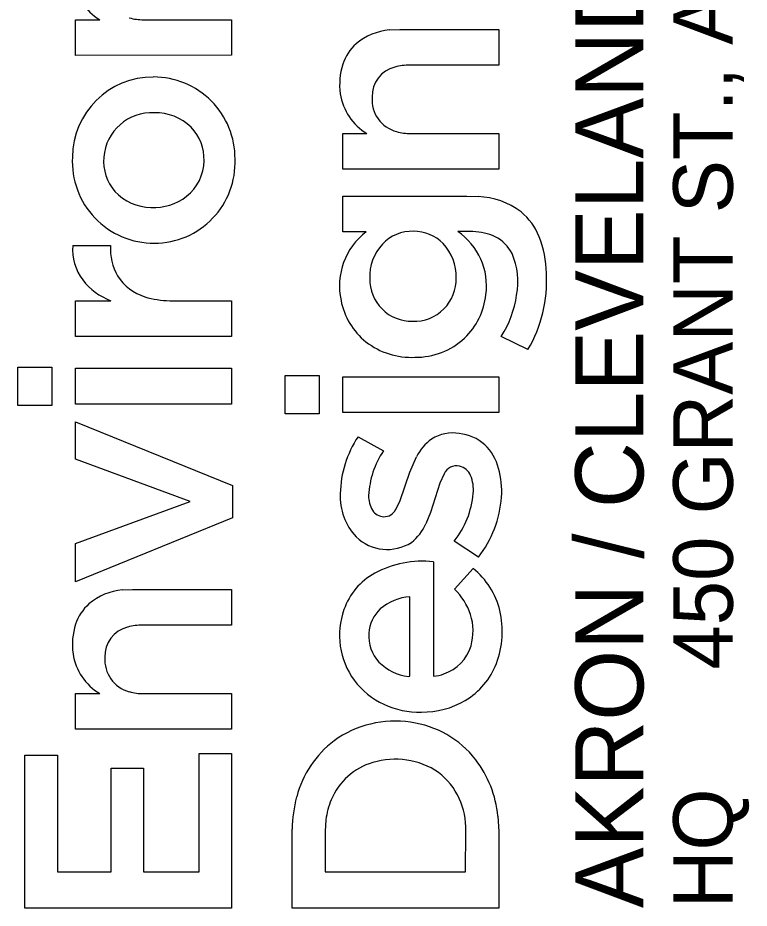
# Model space of a CAD drawing. Extents: x 0 to 34, y 0 to 22.
# Drawn here: x 32.377 to 32.989, y 2.638 to 3.382 of the extents above; entities that cross this region are included whole.
import ezdxf

# ---------------------------------------------------------------- set-up
doc = ezdxf.new("R2010")
doc.units = 0
doc.layers.add('SH_Data', color=7, linetype='Continuous')

msp = doc.modelspace()

# ---------------------------------------------------------------- linework, layer by layer
at = {"layer": 'SH_Data'}
for p, q in [((32.42542, 3.38066), (32.44552, 3.38071)), ((32.42542, 3.35086), (32.42542, 3.38066)), ((32.48222, 3.38071), (32.55569, 3.38071)), ((32.55569, 3.38071), (32.55571, 3.35096)), ((32.68784, 3.3722), (32.69634, 3.37266)), ((32.69634, 3.37266), (32.77916, 3.37266)), ((32.77916, 3.37266), (32.77917, 3.34287)), ((32.55571, 3.35096), (32.42542, 3.35086)), ((32.77917, 3.34287), (32.70485, 3.3428)), ((32.64888, 3.2855), (32.66897, 3.28555)), ((32.64888, 3.25569), (32.64888, 3.2855)), ((32.70568, 3.28555), (32.77915, 3.28555)), ((32.77915, 3.28555), (32.77917, 3.25579)), ((32.77917, 3.25579), (32.64888, 3.25569)), ((32.6489, 3.20336), (32.64889, 3.23322)), ((32.64889, 3.23322), (32.75236, 3.23322)), ((32.75236, 3.23322), (32.76191, 3.23285)), ((32.66836, 3.20336), (32.6489, 3.20336)), ((32.75763, 3.20356), (32.74487, 3.20361)), ((32.42299, 3.19193), (32.45454, 3.19193)), ((32.42542, 3.14577), (32.45473, 3.14579)), ((32.42542, 3.11593), (32.42542, 3.14577)), ((32.50413, 3.14581), (32.55571, 3.14573)), ((32.55571, 3.14573), (32.55565, 3.11593)), ((32.55565, 3.11593), (32.42542, 3.11593)), ((32.8036, 3.10491), (32.7812, 3.11598)), ((32.37705, 3.05818), (32.37705, 3.09026)), ((32.37705, 3.09026), (32.40543, 3.09026)), ((32.40543, 3.09026), (32.40543, 3.05818)), ((32.42542, 3.05942), (32.42542, 3.08928)), ((32.42542, 3.08928), (32.55571, 3.08928)), ((32.55571, 3.08928), (32.55571, 3.05942)), ((32.60051, 3.05111), (32.60051, 3.08319)), ((32.60051, 3.08319), (32.62889, 3.08319)), ((32.62889, 3.08319), (32.62889, 3.05111)), ((32.64888, 3.05234), (32.64888, 3.0822)), ((32.64888, 3.0822), (32.77917, 3.0822)), ((32.77917, 3.0822), (32.77917, 3.05234)), ((32.40543, 3.05818), (32.37705, 3.05818)), ((32.55571, 3.05942), (32.42542, 3.05942)), ((32.77917, 3.05234), (32.64888, 3.05234)), ((32.62889, 3.05111), (32.60051, 3.05111)), ((32.42542, 3.01327), (32.42542, 3.0446)), ((32.42542, 3.0446), (32.5567, 2.9913)), ((32.66151, 3.03207), (32.68268, 3.02025)), ((32.70483, 3.00258), (32.71036, 3.01526)), ((32.52117, 2.97798), (32.42542, 3.01327)), ((32.69675, 2.97868), (32.70483, 3.00258)), ((32.73342, 3.00101), (32.72985, 2.9933)), ((32.72985, 2.9933), (32.72213, 2.96882)), ((32.5567, 2.9913), (32.5567, 2.96441)), ((32.42542, 2.94294), (32.52117, 2.97798)), ((32.69299, 2.97117), (32.69675, 2.97868)), ((32.5567, 2.96441), (32.42542, 2.91086)), ((32.72213, 2.96882), (32.71822, 2.95921)), ((32.42542, 2.91086), (32.42542, 2.94294)), ((32.76214, 2.93141), (32.74198, 2.94469)), ((32.72453, 2.92747), (32.72463, 2.83195)), ((32.74228, 2.90465), (32.75768, 2.922)), ((32.46439, 2.90397), (32.47289, 2.90443)), ((32.47289, 2.90443), (32.55571, 2.90443)), ((32.55571, 2.90443), (32.55571, 2.87465)), ((32.70489, 2.83182), (32.70489, 2.89834)), ((32.55571, 2.87465), (32.4814, 2.87457)), ((32.70361, 2.83165), (32.70489, 2.83182)), ((32.42542, 2.81728), (32.44552, 2.81733)), ((32.42542, 2.78747), (32.42542, 2.81728)), ((32.48222, 2.81733), (32.55569, 2.81733)), ((32.55569, 2.81733), (32.55571, 2.78756)), ((32.55571, 2.78756), (32.42542, 2.78747)), ((32.38298, 2.63791), (32.38298, 2.76598)), ((32.38298, 2.76598), (32.41012, 2.76598)), ((32.41012, 2.76598), (32.41012, 2.66827)), ((32.52857, 2.66827), (32.52857, 2.76722)), ((32.52857, 2.76722), (32.55571, 2.76722)), ((32.55571, 2.76722), (32.55571, 2.63791)), ((32.45503, 2.66827), (32.45503, 2.75488)), ((32.45503, 2.75488), (32.48218, 2.75488)), ((32.48218, 2.75488), (32.48218, 2.66827)), ((32.63465, 2.71178), (32.63407, 2.7023)), ((32.77847, 2.71497), (32.77917, 2.7021)), ((32.60643, 2.63799), (32.60644, 2.704)), ((32.63407, 2.7023), (32.63407, 2.66838)), ((32.75149, 2.66834), (32.75153, 2.70239)), ((32.77917, 2.7021), (32.77917, 2.638)), ((32.41012, 2.66827), (32.45503, 2.66827)), ((32.48218, 2.66827), (32.52857, 2.66827)), ((32.63407, 2.66838), (32.75149, 2.66834)), ((32.55571, 2.63791), (32.38298, 2.63791)), ((32.77917, 2.638), (32.60643, 2.63799))]:
    msp.add_line(p, q, dxfattribs=at)
for points in [[(32.42542, 3.35086), (32.42542, 3.38066), (32.44552, 3.38071)], [(32.48222, 3.38071), (32.55569, 3.38071), (32.55571, 3.35096), (32.42542, 3.35086)], [(32.68784, 3.3722), (32.69634, 3.37266), (32.77916, 3.37266), (32.77917, 3.34287), (32.70485, 3.3428)], [(32.64888, 3.25569), (32.64888, 3.2855), (32.66897, 3.28555)], [(32.70568, 3.28555), (32.77915, 3.28555), (32.77917, 3.25579), (32.64888, 3.25569)], [(32.66836, 3.20336), (32.6489, 3.20336), (32.64889, 3.23322), (32.75236, 3.23322), (32.76191, 3.23285)], [(32.75763, 3.20356), (32.74487, 3.20361)], [(32.42299, 3.19193), (32.45454, 3.19193)], [(32.50413, 3.14581), (32.55571, 3.14573), (32.55565, 3.11593), (32.42542, 3.11593)], [(32.42542, 3.11593), (32.42542, 3.14577), (32.45473, 3.14579)], [(32.8036, 3.10491), (32.7812, 3.11598)], [(32.66151, 3.03207), (32.68268, 3.02025)], [(32.69299, 2.97117), (32.69675, 2.97868), (32.70483, 3.00258), (32.71036, 3.01526)], [(32.73342, 3.00101), (32.72985, 2.9933), (32.72213, 2.96882), (32.71822, 2.95921)], [(32.76214, 2.93141), (32.74198, 2.94469)], [(32.72453, 2.92747), (32.72463, 2.83195)], [(32.74228, 2.90465), (32.75768, 2.922)], [(32.46439, 2.90397), (32.47289, 2.90443), (32.55571, 2.90443), (32.55571, 2.87465), (32.4814, 2.87457)], [(32.70361, 2.83165), (32.70489, 2.83182), (32.70489, 2.89834)], [(32.42542, 2.78747), (32.42542, 2.81728), (32.44552, 2.81733)], [(32.48222, 2.81733), (32.55569, 2.81733), (32.55571, 2.78756), (32.42542, 2.78747)], [(32.77847, 2.71497), (32.77917, 2.7021), (32.77917, 2.638), (32.60643, 2.63799)], [(32.63465, 2.71178), (32.63407, 2.7023), (32.63407, 2.66838), (32.75149, 2.66834), (32.75153, 2.70239)], [(32.60643, 2.63799), (32.60644, 2.704)]]:
    msp.add_lwpolyline(points, dxfattribs=at)
for points in [[(32.37705, 3.05818), (32.37705, 3.09026), (32.40543, 3.09026), (32.40543, 3.05818)], [(32.42542, 3.05942), (32.42542, 3.08928), (32.55571, 3.08928), (32.55571, 3.05942)], [(32.60051, 3.05111), (32.60051, 3.08319), (32.62889, 3.08319), (32.62889, 3.05111)], [(32.64888, 3.05234), (32.64888, 3.0822), (32.77917, 3.0822), (32.77917, 3.05234)], [(32.42542, 2.91086), (32.42542, 2.94294), (32.52117, 2.97798), (32.42542, 3.01327), (32.42542, 3.0446), (32.5567, 2.9913), (32.5567, 2.96441)], [(32.38298, 2.63791), (32.38298, 2.76598), (32.41012, 2.76598), (32.41012, 2.66827), (32.45503, 2.66827), (32.45503, 2.75488), (32.48218, 2.75488), (32.48218, 2.66827), (32.52857, 2.66827), (32.52857, 2.76722), (32.55571, 2.76722), (32.55571, 2.63791)]]:
    msp.add_lwpolyline(points, close=True, dxfattribs=at)
for centre, radius, start, end in [((32.47027, 3.42141), 0.04763, 188.96462, 238.69865), ((32.47027, 3.42141), 0.04763, 188.96462, 238.69865), ((32.48183, 3.42286), 0.04215, 254.08913, 270.52838), ((32.48183, 3.42286), 0.04215, 254.08913, 270.52838), ((32.69216, 3.32251), 0.04988, 94.97056, 130.22484), ((32.69216, 3.32251), 0.04988, 94.97056, 130.22484), ((32.68694, 3.33085), 0.04016, 132.22383, 161.68229), ((32.68694, 3.33085), 0.04016, 132.22383, 161.68229), ((32.70217, 3.32642), 0.05602, 162.27398, 187.79173), ((32.70217, 3.32642), 0.05602, 162.27398, 187.79173), ((32.70453, 3.29679), 0.04601, 89.60515, 105.33026), ((32.70453, 3.29679), 0.04601, 89.60515, 105.33026), ((32.69828, 3.31689), 0.02498, 103.68683, 182.21395), ((32.69828, 3.31689), 0.02498, 103.68683, 182.21395), ((32.49014, 3.26543), 0.0674, 89.84756, 179.64047), ((32.49014, 3.26543), 0.0674, 89.84756, 179.64047), ((32.49057, 3.26474), 0.0681, 359.54009, 90.21138), ((32.49057, 3.26474), 0.0681, 359.54009, 90.21138), ((32.69372, 3.32624), 0.04763, 188.96462, 238.69865), ((32.69372, 3.32624), 0.04763, 188.96462, 238.69865), ((32.7008, 3.31381), 0.02757, 175.58441, 255.13816), ((32.7008, 3.31381), 0.02757, 175.58441, 255.13816), ((32.48923, 3.26263), 0.0404, 87.04809, 175.57259), ((32.48923, 3.26263), 0.0404, 87.04809, 175.57259), ((32.49204, 3.25999), 0.04299, 45.84264, 90.98008), ((32.49204, 3.25999), 0.04299, 45.84264, 90.98008), ((32.49458, 3.26421), 0.03821, 357.88569, 44.15902), ((32.49458, 3.26421), 0.03821, 357.88569, 44.15902), ((32.70529, 3.32769), 0.04215, 254.08913, 270.52838), ((32.70529, 3.32769), 0.04215, 254.08913, 270.52838), ((32.49083, 3.26209), 0.06819, 176.8344, 270.40384), ((32.49083, 3.26209), 0.06819, 176.8344, 270.40384), ((32.48729, 3.2625), 0.03848, 175.15378, 221.14706), ((32.48729, 3.2625), 0.03848, 175.15378, 221.14706), ((32.49123, 3.26139), 0.06749, 270.06243, 2.37759), ((32.49123, 3.26139), 0.06749, 270.06243, 2.37759), ((32.49446, 3.26318), 0.0383, 308.28936, 359.43468), ((32.49446, 3.26318), 0.0383, 308.28936, 359.43468), ((32.48919, 3.26607), 0.04228, 223.09994, 268.80895), ((32.48919, 3.26607), 0.04228, 223.09994, 268.80895), ((32.49096, 3.2679), 0.04418, 266.56515, 308.06078), ((32.49096, 3.2679), 0.04418, 266.56515, 308.06078), ((32.75907, 3.16789), 0.06503, 53.40344, 87.49062), ((32.75907, 3.16789), 0.06503, 53.40344, 87.49062), ((32.76517, 3.18039), 0.05141, 21.60748, 50.5577), ((32.76517, 3.18039), 0.05141, 21.60748, 50.5577), ((32.70292, 3.15813), 0.05692, 127.37482, 192.22468), ((32.70292, 3.15813), 0.05692, 127.37482, 192.22468), ((32.70693, 3.16927), 0.0346, 88.47302, 136.42562), ((32.70693, 3.16927), 0.0346, 88.47302, 136.42562), ((32.70814, 3.16963), 0.03424, 44.27195, 90.47623), ((32.70814, 3.16963), 0.03424, 44.27195, 90.47623), ((32.71421, 3.15829), 0.05472, 352.1125, 55.92295), ((32.71421, 3.15829), 0.05472, 352.1125, 55.92295), ((32.75666, 3.15725), 0.04633, 65.01687, 88.8011), ((32.75666, 3.15725), 0.04633, 65.01687, 88.8011), ((32.7626, 3.17155), 0.03085, 26.26808, 63.80301), ((32.7626, 3.17155), 0.03085, 26.26808, 63.80301), ((32.73069, 3.16714), 0.08835, 1.15143, 21.3627), ((32.73069, 3.16714), 0.08835, 1.15143, 21.3627), ((32.46616, 3.18882), 0.04329, 175.87313, 216.34747), ((32.46616, 3.18882), 0.04329, 175.87313, 216.34747), ((32.50087, 3.18948), 0.04639, 176.9688, 209.60636), ((32.50087, 3.18948), 0.04639, 176.9688, 209.60636), ((32.71141, 3.16602), 0.0401, 137.46739, 182.33237), ((32.71141, 3.16602), 0.0401, 137.46739, 182.33237), ((32.70368, 3.166), 0.03996, 358.57141, 43.53765), ((32.70368, 3.166), 0.03996, 358.57141, 43.53765), ((32.73565, 3.16154), 0.05953, 349.30734, 23.43071), ((32.73565, 3.16154), 0.05953, 349.30734, 23.43071), ((32.49514, 3.18814), 0.04079, 211.94466, 253.2028), ((32.49514, 3.18814), 0.04079, 211.94466, 253.2028), ((32.70645, 3.1637), 0.03511, 178.88208, 271.08374), ((32.70645, 3.1637), 0.03511, 178.88208, 271.08374), ((32.70818, 3.16404), 0.03546, 268.27882, 1.55016), ((32.70818, 3.16404), 0.03546, 268.27882, 1.55016), ((32.70538, 3.16244), 0.11383, 329.6388, 3.25998), ((32.70538, 3.16244), 0.11383, 329.6388, 3.25998), ((32.47466, 3.19716), 0.05511, 218.09809, 248.7907), ((32.47466, 3.19716), 0.05511, 218.09809, 248.7907), ((32.50465, 3.2165), 0.07069, 252.46555, 269.57296), ((32.50465, 3.2165), 0.07069, 252.46555, 269.57296), ((32.70988, 3.15708), 0.05887, 313.74196, 353.8554), ((32.70988, 3.15708), 0.05887, 313.74196, 353.8554), ((32.70738, 3.16334), 0.08771, 327.31495, 351.57478), ((32.70738, 3.16334), 0.08771, 327.31495, 351.57478), ((32.70463, 3.15696), 0.05837, 190.75182, 231.28919), ((32.70463, 3.15696), 0.05837, 190.75182, 231.28919), ((32.70954, 3.15901), 0.06051, 269.6361, 312.70877), ((32.70954, 3.15901), 0.06051, 269.6361, 312.70877), ((32.70632, 3.16112), 0.06269, 232.46061, 272.59022), ((32.70632, 3.16112), 0.06269, 232.46061, 272.59022), ((32.73636, 2.98258), 0.08973, 146.53104, 178.7571), ((32.73636, 2.98258), 0.08973, 146.53104, 178.7571), ((32.74661, 2.99713), 0.04053, 125.51182, 153.41595), ((32.74661, 2.99713), 0.04053, 125.51182, 153.41595), ((32.7406, 3.0026), 0.03263, 80.17192, 122.51969), ((32.7406, 3.0026), 0.03263, 80.17192, 122.51969), ((32.74278, 2.99824), 0.03667, 47.79344, 84.68918), ((32.74278, 2.99824), 0.03667, 47.79344, 84.68918), ((32.73788, 2.9946), 0.04267, 14.9966, 46.20632), ((32.73788, 2.9946), 0.04267, 14.9966, 46.20632), ((32.74519, 2.9789), 0.07495, 146.51121, 176.91007), ((32.74519, 2.9789), 0.07495, 146.51121, 176.91007), ((32.74384, 2.99631), 0.01143, 76.66094, 155.7053), ((32.74384, 2.99631), 0.01143, 76.66094, 155.7053), ((32.74397, 2.99511), 0.01256, 21.5098, 78.52618), ((32.74397, 2.99511), 0.01256, 21.5098, 78.52618), ((32.71044, 2.98674), 0.07121, 355.83062, 15.39138), ((32.71044, 2.98674), 0.07121, 355.83062, 15.39138), ((32.72592, 2.98766), 0.03209, 354.57264, 22.06805), ((32.72592, 2.98766), 0.03209, 354.57264, 22.06805), ((32.69666, 2.98238), 0.05005, 177.53659, 222.79318), ((32.69666, 2.98238), 0.05005, 177.53659, 222.79318), ((32.6931, 2.98233), 0.02276, 178.47474, 211.08679), ((32.6931, 2.98233), 0.02276, 178.47474, 211.08679), ((32.68248, 2.99149), 0.0757, 321.81101, 354.79685), ((32.68248, 2.99149), 0.0757, 321.81101, 354.79685), ((32.68952, 2.9882), 0.09219, 321.9777, 355.87384), ((32.68952, 2.9882), 0.09219, 321.9777, 355.87384), ((32.68331, 2.9767), 0.01148, 212.23676, 268.37769), ((32.68331, 2.9767), 0.01148, 212.23676, 268.37769), ((32.68342, 2.97589), 0.01067, 267.71603, 333.73375), ((32.68342, 2.97589), 0.01067, 267.71603, 333.73375), ((32.68098, 2.9758), 0.04077, 308.08772, 335.98736), ((32.68098, 2.9758), 0.04077, 308.08772, 335.98736), ((32.68599, 2.97535), 0.0375, 225.98539, 302.47965), ((32.68599, 2.97535), 0.0375, 225.98539, 302.47965), ((32.7152, 2.84414), 0.08384, 83.61499, 118.28755), ((32.7152, 2.84414), 0.08384, 83.61499, 118.28755), ((32.71744, 2.87167), 0.06443, 13.53365, 51.36148), ((32.71744, 2.87167), 0.06443, 13.53365, 51.36148), ((32.70239, 2.86906), 0.05583, 118.83082, 160.62438), ((32.70239, 2.86906), 0.05583, 118.83082, 160.62438), ((32.46871, 2.85428), 0.04988, 94.96958, 130.22249), ((32.46871, 2.85428), 0.04988, 94.96958, 130.22249), ((32.70378, 2.86556), 0.05486, 19.03571, 45.44059), ((32.70378, 2.86556), 0.05486, 19.03571, 45.44059), ((32.70785, 2.85609), 0.04235, 94.00805, 130.88169), ((32.70785, 2.85609), 0.04235, 94.00805, 130.88169), ((32.46348, 2.86263), 0.04015, 132.22192, 161.68183), ((32.46348, 2.86263), 0.04015, 132.22192, 161.68183), ((32.71041, 2.86612), 0.06437, 160.52012, 215.78311), ((32.71041, 2.86612), 0.06437, 160.52012, 215.78311), ((32.70048, 2.86628), 0.02985, 132.98507, 177.179), ((32.70048, 2.86628), 0.02985, 132.98507, 177.179), ((32.71069, 2.8697), 0.047, 344.60586, 17.007), ((32.71069, 2.8697), 0.047, 344.60586, 17.007), ((32.70635, 2.86921), 0.07579, 339.3542, 13.37853), ((32.70635, 2.86921), 0.07579, 339.3542, 13.37853), ((32.47872, 2.85819), 0.05601, 162.27355, 187.79185), ((32.47872, 2.85819), 0.05601, 162.27355, 187.79185), ((32.48108, 2.82856), 0.04601, 89.60494, 105.3284), ((32.48108, 2.82856), 0.04601, 89.60494, 105.3284), ((32.47482, 2.84867), 0.02498, 103.68646, 182.21874), ((32.47482, 2.84867), 0.02498, 103.68646, 182.21874), ((32.7017, 2.86503), 0.03115, 175.00126, 223.28301), ((32.7017, 2.86503), 0.03115, 175.00126, 223.28301), ((32.7224, 2.86715), 0.03504, 288.00773, 343.55078), ((32.7224, 2.86715), 0.03504, 288.00773, 343.55078), ((32.47026, 2.85802), 0.04762, 188.96199, 238.70369), ((32.47026, 2.85802), 0.04762, 188.96199, 238.70369), ((32.47735, 2.84558), 0.02756, 175.58538, 255.14386), ((32.47735, 2.84558), 0.02756, 175.58538, 255.14386), ((32.70891, 2.87363), 0.04231, 225.06188, 262.79738), ((32.70891, 2.87363), 0.04231, 225.06188, 262.79738), ((32.71894, 2.8652), 0.0626, 300.94269, 338.73225), ((32.71894, 2.8652), 0.0626, 300.94269, 338.73225), ((32.72474, 2.85216), 0.02021, 269.7003, 294.8711), ((32.72474, 2.85216), 0.02021, 269.7003, 294.8711), ((32.71253, 2.87054), 0.06872, 217.74516, 271.65431), ((32.71253, 2.87054), 0.06872, 217.74516, 271.65431), ((32.48183, 2.85948), 0.04215, 254.09162, 270.52835), ((32.48183, 2.85948), 0.04215, 254.09162, 270.52835), ((32.71549, 2.87241), 0.07056, 269.20477, 300.33412), ((32.71549, 2.87241), 0.07056, 269.20477, 300.33412), ((32.69229, 2.70792), 0.08641, 81.19402, 125.99844), ((32.69229, 2.70792), 0.08641, 81.19402, 125.99844), ((32.69458, 2.71132), 0.08272, 37.85208, 82.40204), ((32.69458, 2.71132), 0.08272, 37.85208, 82.40204), ((32.69387, 2.70893), 0.08654, 127.23621, 165.14796), ((32.69387, 2.70893), 0.08654, 127.23621, 165.14796), ((32.69279, 2.69862), 0.06389, 55.67272, 107.20935), ((32.69279, 2.69862), 0.06389, 55.67272, 107.20935), ((32.68586, 2.70567), 0.09308, 5.73329, 37.30396), ((32.68586, 2.70567), 0.09308, 5.73329, 37.30396), ((32.68893, 2.70782), 0.05398, 106.18808, 157.38609), ((32.68893, 2.70782), 0.05398, 106.18808, 157.38609), ((32.69291, 2.70499), 0.05867, 357.46616, 52.26647), ((32.69291, 2.70499), 0.05867, 357.46616, 52.26647), ((32.71426, 2.70281), 0.10783, 164.7861, 179.37039), ((32.71426, 2.70281), 0.10783, 164.7861, 179.37039), ((32.69829, 2.70389), 0.06412, 157.35705, 172.92755), ((32.69829, 2.70389), 0.06412, 157.35705, 172.92755)]:
    msp.add_arc(centre, radius, start, end, dxfattribs=at)

# ---------------------------------------------------------------- texts
for s, height, p in [('450 GRANT ST., AKRON, OH  44311', 0.0498462, (32.97489, 2.83738)), ('AKRON / CLEVELAND / COLUMBUS', 0.056969, (32.90012, 2.638)), ('HQ ', 0.049846, (32.97489, 2.638))]:
    msp.add_text(s, height=height, rotation=90, dxfattribs=at).set_placement(p)

doc.saveas('drawing.dxf')
